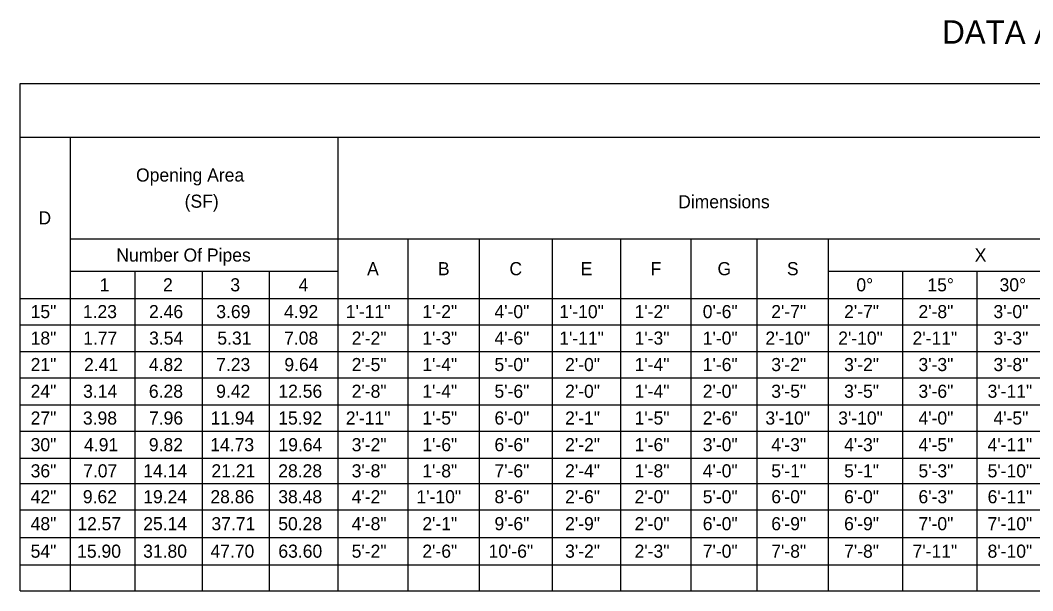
# Model space of a CAD drawing. Extents: x 10029 to 10796, y 10063 to 10519.
# Drawn here: x 10029 to 10299.4, y 10366.5 to 10518.9 of the extents above; entities that cross this region are included whole.
import ezdxf

# ---------------------------------------------------------------- set-up
doc = ezdxf.new("R2010")
doc.units = 0
doc.layers.add('Default', color=7, linetype='Continuous')
doc.layers.add('TextStructures', color=7, linetype='Continuous')

msp = doc.modelspace()

# ---------------------------------------------------------------- linework, layer by layer
at = {"layer": 'Default'}
for p, q in [((10028.97, 10502.01), (10795.89, 10502.01)), ((10028.97, 10366.47), (10028.97, 10502.01)), ((10028.97, 10487.65), (10795.89, 10487.65)), ((10042.36, 10366.47), (10042.36, 10487.65)), ((10113.89, 10366.47), (10113.89, 10487.65)), ((10042.36, 10460.49), (10783.03, 10460.49)), ((10132.57, 10366.47), (10132.57, 10460.49)), ((10151.63, 10366.47), (10151.63, 10460.49)), ((10171.07, 10366.47), (10171.07, 10460.49)), ((10189.38, 10366.47), (10189.38, 10460.49)), ((10208.18, 10366.47), (10208.18, 10460.49)), ((10225.79, 10366.47), (10225.79, 10460.49)), ((10244.78, 10366.47), (10244.78, 10460.49)), ((10042.36, 10451.88), (10113.89, 10451.88)), ((10059.62, 10366.47), (10059.62, 10451.88)), ((10077.6, 10366.47), (10077.6, 10451.88)), ((10095.57, 10366.47), (10095.57, 10451.88)), ((10244.78, 10451.88), (10783.03, 10451.88)), ((10264.68, 10366.47), (10264.68, 10451.88)), ((10284.51, 10366.47), (10284.51, 10451.88)), ((10028.97, 10444.58), (10795.89, 10444.58)), ((10028.97, 10437.55), (10795.89, 10437.55)), ((10028.97, 10430.43), (10795.89, 10430.43)), ((10028.97, 10423.41), (10795.89, 10423.41)), ((10028.97, 10416.18), (10795.89, 10416.18)), ((10028.97, 10409.08), (10795.89, 10409.08)), ((10028.97, 10401.92), (10795.89, 10401.92)), ((10028.97, 10395.12), (10795.89, 10395.12)), ((10028.97, 10388.08), (10795.89, 10388.08)), ((10028.97, 10380.7), (10795.89, 10380.7)), ((10028.97, 10373.4), (10795.89, 10373.4)), ((10028.97, 10366.47), (10795.89, 10366.47))]:
    msp.add_line(p, q, dxfattribs=at)

# ---------------------------------------------------------------- texts
at = {"layer": 'TextStructures'}
for s, height, rotation, p in [('DATA AND ESTIMATED QUANTITIES FOR ONE ENDWALL', 6.25, 359.7555, (10275.18, 10512.68)), ('15"', 3.5, 0, (10031.74, 10439.32)), ('1.23', 3.5, 0, (10045.69, 10439.32)), ('2.46', 3.5, 0, (10063.35, 10439.32)), ('3.69', 3.5, 0, (10081.32, 10439.32)), ('4.92', 3.5, 0, (10099.43, 10439.32)), ('1\'-11"', 3.5, 0, (10115.91, 10439.32)), ('1\'-2"', 3.5, 0, (10136.35, 10439.32)), ('4\'-0"', 3.5, 0, (10155.61, 10439.32)), ('1\'-10"', 3.5, 0, (10172.91, 10439.32)), ('1\'-2"', 3.5, 0, (10193.04, 10439.32)), ('0\'-6"', 3.5, 0, (10211.24, 10439.32)), ('2\'-7"', 3.5, 0, (10229.54, 10439.32)), ('2\'-7"', 3.5, 0, (10248.99, 10439.32)), ('2\'-8"', 3.5, 0, (10268.85, 10439.32)), ('3\'-0"', 3.5, 0, (10288.88, 10439.32)), ('18"', 3.5, 0, (10031.74, 10432.24)), ('1.77', 3.5, 0, (10045.77, 10432.24)), ('3.54', 3.5, 0, (10063.38, 10432.24)), ('5.31', 3.5, 0, (10081.6, 10432.24)), ('7.08', 3.5, 0, (10099.44, 10432.24)), ('2\'-2"', 3.5, 0, (10117.48, 10432.24)), ('1\'-3"', 3.5, 0, (10136.35, 10432.24)), ('4\'-6"', 3.5, 0, (10155.61, 10432.24)), ('1\'-11"', 3.5, 0, (10172.91, 10432.24)), ('1\'-3"', 3.5, 0, (10193.04, 10432.24)), ('1\'-0"', 3.5, 0, (10211.24, 10432.24)), ('2\'-10"', 3.5, 0, (10227.97, 10432.24)), ('2\'-10"', 3.5, 0, (10247.42, 10432.24)), ('2\'-11"', 3.5, 0, (10267.28, 10432.24)), ('3\'-3"', 3.5, 0, (10288.88, 10432.24)), ('21"', 3.5, 0, (10031.74, 10425.17)), ('2.41', 3.5, 0, (10046.01, 10425.17)), ('4.82', 3.5, 0, (10063.31, 10425.17)), ('7.23', 3.5, 0, (10081.29, 10425.17)), ('9.64', 3.5, 0, (10099.5, 10425.17)), ('2\'-5"', 3.5, 0, (10117.48, 10425.17)), ('1\'-4"', 3.5, 0, (10136.35, 10425.17)), ('5\'-0"', 3.5, 0, (10155.61, 10425.17)), ('2\'-0"', 3.5, 0, (10174.48, 10425.17)), ('1\'-4"', 3.5, 0, (10193.04, 10425.17)), ('1\'-6"', 3.5, 0, (10211.24, 10425.17)), ('3\'-2"', 3.5, 0, (10229.54, 10425.17)), ('3\'-2"', 3.5, 0, (10248.99, 10425.17)), ('3\'-3"', 3.5, 0, (10268.85, 10425.17)), ('3\'-8"', 3.5, 0, (10288.88, 10425.17)), ('24"', 3.5, 0, (10031.74, 10418.04)), ('3.14', 3.5, 0, (10045.76, 10418.04)), ('6.28', 3.5, 0, (10063.32, 10418.04)), ('9.42', 3.5, 0, (10081.29, 10418.04)), ('12.56', 3.5, 0, (10097.9, 10418.04)), ('2\'-8"', 3.5, 0, (10117.48, 10418.04)), ('1\'-4"', 3.5, 0, (10136.35, 10418.04)), ('5\'-6"', 3.5, 0, (10155.61, 10418.04)), ('2\'-0"', 3.5, 0, (10174.48, 10418.04)), ('1\'-4"', 3.5, 0, (10193.04, 10418.04)), ('2\'-0"', 3.5, 0, (10211.24, 10418.04)), ('3\'-5"', 3.5, 0, (10229.54, 10418.04)), ('3\'-5"', 3.5, 0, (10248.99, 10418.04)), ('3\'-6"', 3.5, 0, (10268.85, 10418.04)), ('3\'-11"', 3.5, 0, (10287.31, 10418.04)), ('27"', 3.5, 0, (10031.74, 10410.88)), ('3.98', 3.5, 0, (10045.7, 10410.88)), ('7.96', 3.5, 0, (10063.35, 10410.88)), ('11.94', 3.5, 0, (10079.79, 10410.88)), ('15.92', 3.5, 0, (10097.86, 10410.88)), ('2\'-11"', 3.5, 0, (10115.91, 10410.88)), ('1\'-5"', 3.5, 0, (10136.35, 10410.88)), ('6\'-0"', 3.5, 0, (10155.61, 10410.88)), ('2\'-1"', 3.5, 0, (10174.48, 10410.88)), ('1\'-5"', 3.5, 0, (10193.04, 10410.88)), ('2\'-6"', 3.5, 0, (10211.24, 10410.88)), ('3\'-10"', 3.5, 0, (10227.97, 10410.88)), ('3\'-10"', 3.5, 0, (10247.42, 10410.88)), ('4\'-0"', 3.5, 0, (10268.85, 10410.88)), ('4\'-5"', 3.5, 0, (10288.88, 10410.88)), ('30"', 3.5, 0, (10031.74, 10403.75)), ('4.91', 3.5, 0, (10046.01, 10403.75)), ('9.82', 3.5, 0, (10063.31, 10403.75)), ('14.73', 3.5, 0, (10079.71, 10403.75)), ('19.64', 3.5, 0, (10097.93, 10403.75)), ('3\'-2"', 3.5, 0, (10117.48, 10403.75)), ('1\'-6"', 3.5, 0, (10136.35, 10403.75)), ('6\'-6"', 3.5, 0, (10155.61, 10403.75)), ('2\'-2"', 3.5, 0, (10174.48, 10403.75)), ('1\'-6"', 3.5, 0, (10193.04, 10403.75)), ('3\'-0"', 3.5, 0, (10211.24, 10403.75)), ('4\'-3"', 3.5, 0, (10229.54, 10403.75)), ('4\'-3"', 3.5, 0, (10248.99, 10403.75)), ('4\'-5"', 3.5, 0, (10268.85, 10403.75)), ('4\'-11"', 3.5, 0, (10287.31, 10403.75)), ('36"', 3.5, 0, (10031.74, 10396.77)), ('7.07', 3.5, 0, (10045.77, 10396.77)), ('14.14', 3.5, 0, (10061.81, 10396.77)), ('21.21', 3.5, 0, (10080.03, 10396.77)), ('28.28', 3.5, 0, (10097.87, 10396.77)), ('3\'-8"', 3.5, 0, (10117.48, 10396.77)), ('1\'-8"', 3.5, 0, (10136.35, 10396.77)), ('7\'-6"', 3.5, 0, (10155.61, 10396.77)), ('2\'-4"', 3.5, 0, (10174.48, 10396.77)), ('1\'-8"', 3.5, 0, (10193.04, 10396.77)), ('4\'-0"', 3.5, 0, (10211.24, 10396.77)), ('5\'-1"', 3.5, 0, (10229.54, 10396.77)), ('5\'-1"', 3.5, 0, (10248.99, 10396.77)), ('5\'-3"', 3.5, 0, (10268.85, 10396.77)), ('5\'-10"', 3.5, 0, (10287.31, 10396.77)), ('42"', 3.5, 0, (10031.74, 10389.85)), ('9.62', 3.5, 0, (10045.69, 10389.85)), ('19.24', 3.5, 0, (10061.81, 10389.85)), ('28.86', 3.5, 0, (10079.75, 10389.85)), ('38.48', 3.5, 0, (10097.87, 10389.85)), ('4\'-2"', 3.5, 0, (10117.48, 10389.85)), ('1\'-10"', 3.5, 0, (10134.78, 10389.85)), ('8\'-6"', 3.5, 0, (10155.61, 10389.85)), ('2\'-6"', 3.5, 0, (10174.48, 10389.85)), ('2\'-0"', 3.5, 0, (10193.04, 10389.85)), ('5\'-0"', 3.5, 0, (10211.24, 10389.85)), ('6\'-0"', 3.5, 0, (10229.54, 10389.85)), ('6\'-0"', 3.5, 0, (10248.99, 10389.85)), ('6\'-3"', 3.5, 0, (10268.85, 10389.85)), ('6\'-11"', 3.5, 0, (10287.31, 10389.85)), ('48"', 3.5, 0, (10031.74, 10382.64)), ('12.57', 3.5, 0, (10044.2, 10382.64)), ('25.14', 3.5, 0, (10061.81, 10382.64)), ('37.71', 3.5, 0, (10080.03, 10382.64)), ('50.28', 3.5, 0, (10097.87, 10382.64)), ('4\'-8"', 3.5, 0, (10117.48, 10382.64)), ('2\'-1"', 3.5, 0, (10136.35, 10382.64)), ('9\'-6"', 3.5, 0, (10155.61, 10382.64)), ('2\'-9"', 3.5, 0, (10174.48, 10382.64)), ('2\'-0"', 3.5, 0, (10193.04, 10382.64)), ('6\'-0"', 3.5, 0, (10211.24, 10382.64)), ('6\'-9"', 3.5, 0, (10229.54, 10382.64)), ('6\'-9"', 3.5, 0, (10248.99, 10382.64)), ('7\'-0"', 3.5, 0, (10268.85, 10382.64)), ('7\'-10"', 3.5, 0, (10287.31, 10382.64)), ('54"', 3.5, 0, (10031.74, 10375.3)), ('15.90', 3.5, 0, (10044.16, 10375.3)), ('31.80', 3.5, 0, (10061.79, 10375.3)), ('47.70', 3.5, 0, (10079.76, 10375.3)), ('63.60', 3.5, 0, (10097.9, 10375.3)), ('5\'-2"', 3.5, 0, (10117.48, 10375.3)), ('2\'-6"', 3.5, 0, (10136.35, 10375.3)), ('10\'-6"', 3.5, 0, (10154.03, 10375.3)), ('3\'-2"', 3.5, 0, (10174.48, 10375.3)), ('2\'-3"', 3.5, 0, (10193.04, 10375.3)), ('7\'-0"', 3.5, 0, (10211.24, 10375.3)), ('7\'-8"', 3.5, 0, (10229.54, 10375.3)), ('7\'-8"', 3.5, 0, (10248.99, 10375.3)), ('7\'-11"', 3.5, 0, (10267.28, 10375.3)), ('8\'-10"', 3.5, 0, (10287.31, 10375.3))]:
    msp.add_text(s, height=height, rotation=rotation, dxfattribs=at).set_placement(p)
for s, p in [('Opening Area', (10059.89, 10475.82)), ('(SF)', (10072.87, 10468.82)), ('Dimensions', (10204.67, 10468.68)), ('D', (10033.83, 10464.37)), ('Number Of Pipes', (10054.63, 10454.43)), ('X', (10283.88, 10454.43)), ('A', (10121.6, 10450.79)), ('B', (10140.51, 10450.79)), ('C', (10159.61, 10450.79)), ('E', (10178.64, 10450.79)), ('F', (10197.29, 10450.79)), ('G', (10215.18, 10450.79)), ('S', (10233.72, 10450.79)), ('1', (10050.18, 10446.48)), ('2', (10067.1, 10446.48)), ('3', (10085.07, 10446.48)), ('4', (10103.3, 10446.48)), ('0°', (10252.27, 10446.48)), ('15°', (10271.24, 10446.48)), ('30°', (10290.51, 10446.48))]:
    msp.add_text(s, height=3.5, dxfattribs=at).set_placement(p)

doc.saveas('drawing.dxf')
